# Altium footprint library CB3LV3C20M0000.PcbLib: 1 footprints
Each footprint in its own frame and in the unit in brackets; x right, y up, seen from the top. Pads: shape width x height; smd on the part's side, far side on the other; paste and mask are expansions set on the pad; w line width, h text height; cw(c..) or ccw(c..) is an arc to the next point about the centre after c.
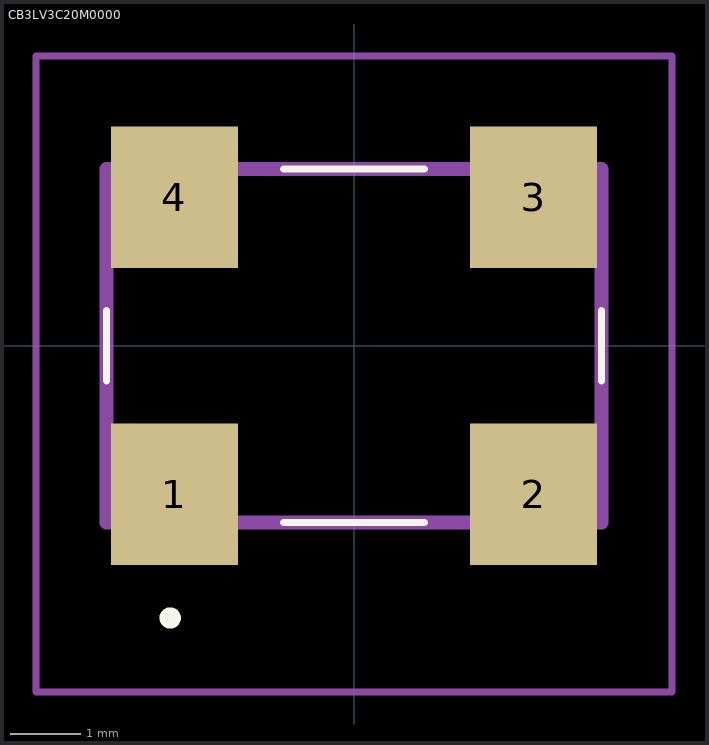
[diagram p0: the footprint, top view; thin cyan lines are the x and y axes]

## CB3LV3C20M0000 [mm]
pads (4):
  rect 1.8x2 smd: 1(-2.54,-2.1) 2(2.54,-2.1) 3(2.54,2.1) 4(-2.54,2.1)
Top Overlay:
  lines w0.1: -3.5,-0.5 -3.5,0.5 ; -3.5,-0.5 -3.5,-0.5 ; -3.5,-0.5 -3.5,0.5 ; -3.5,0.5 -3.5,0.5 ; -1,-2.5 1,-2.5 ; -1,-2.5 1,-2.5 ; -1,-2.5 -1,-2.5 ; -1,2.5 1,2.5 ; -1,2.5 1,2.5 ; -1,2.5 -1,2.5 ; 1,-2.5 1,-2.5 ; 1,2.5 1,2.5 ; 3.5,-0.5 3.5,0.5 ; 3.5,-0.5 3.5,-0.5 ; 3.5,-0.5 3.5,0.5 ; 3.5,0.5 3.5,0.5
  lines w0.2: -2.6,-3.9 -2.6,-3.9 ; -2.6,-3.9 ccw(c-2.6,-3.85) -2.6,-3.8 ; -2.6,-3.9 cw(c-2.6,-3.85) -2.6,-3.8 ; -2.6,-3.9 -2.6,-3.9 ; -2.6,-3.9 ccw(c-2.6,-3.85) -2.6,-3.8 ; -2.6,-3.8 -2.6,-3.8
Mechanical 15:
  lines w0.2: -3.5,-2.5 3.5,-2.5 3.5,2.5 -3.5,2.5 -3.5,-2.5
Mechanical 20:
  lines w0.1: -4.5,-4.9 4.5,-4.9 4.5,4.1 -4.5,4.1 -4.5,-4.9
